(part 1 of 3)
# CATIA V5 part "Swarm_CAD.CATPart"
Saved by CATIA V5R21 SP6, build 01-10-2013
Part number: Final_Swarm
Bounding box of the stored display mesh (mm): x -2100 to 7123.12, y -825.75 to 825.75, z -676.575 to 779.691
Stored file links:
  O:\Swarm_G_March\Swarm_CAD_CATIA.CATPart
  D:\gmarch\Desktop\SWARM\CATPart_single_body.CATPart
  D:\gmarch\Desktop\SWARM\Final_Swarm_for_rendering.CATPart
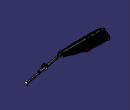
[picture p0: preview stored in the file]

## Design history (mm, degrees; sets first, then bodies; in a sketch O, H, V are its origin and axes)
Set1
  Plane1: type Offset, RefPlane yz-plane, Offset 2945.11
  Sketch1 on Plane1, origin (2945.11, 0, 0), H (0, 1, 0), V (0, 0, 1)
    point P1 (-825.75, -46.32)
    line L1 (-825.75, -46.32) -> (-113.815, 470.931)
    line L2 (-113.815, 470.931) -> (113.815, 470.931)
    line L3 (113.815, 470.931) -> (825.75, -46.32)
    point P4 (825.75, -46.32)
    line L4 (825.75, -46.32) -> (811.0554, -66.5454)
    point P5 (811.0554, -66.5454)
    line L5 (811.0554, -66.5454) -> (665, 39.57)
    point P6 (665, 39.57)
    line L6 (665, 39.57) -> (665, -300)
    line L7 (665, -300) -> (-665, -300)
    line L8 (-665, -300) -> (-665, 39.57)
    point P9 (-665, 39.57)
    line L9 (-665, 39.57) -> (-811.0554, -66.5454)
    point P10 (-811.0554, -66.5454)
    line L10 (-811.0554, -66.5454) -> (-825.75, -46.32)
    distance L7 H = 300
    distance P1 L7 = 253.68
    distance P4 L7 = 253.68
    distance L8 L6 = 1330
    distance L8 V = 665
    angle L1 V = 54
    angle L3 V = 54
    distance P1 P4 = 1651.5
    distance P6 P9 V = 0
    angle L5 L4 = 90
    distance P10 P5 V = 0
    distance L5 L3 = 25
    length L1 = 880
    horizontal: L2 H, L7 H
    vertical: L6 V, L8 V
    perpendicularity: L10 L1
    parallelism: L1 L9
  Sketch2 on end face of Pad1, origin (-2000, 0, 0), H (0, -1, 0), V (0, 0, 1)
    point P1 (-113.815, 470.931)
    line L1 (-113.815, 470.931) -> (-96.1815, 446.6605)
    line L2 (-96.1815, 446.6605) -> (-88.7678, 470.931)
    point P3 (-88.7678, 470.931)
    line L3 (-88.7678, 470.931) -> (-100, 480)
    line L4 (-100, 480) -> (-113.815, 470.931)
    reference projected line E1 (-825.75, -46.32) -> (-113.815, 470.931) from edge [end face of Pad1 | face of Mirror1]
    reference projected point E2 (-113.815, 470.931) from vertex [face of Pad1 from Sketch1.L2 | end face of Pad1 | face of Pad1 from Sketch1.L3]
    reference projected line E3 (-113.815, 470.931) -> (113.815, 470.931) from edge [end face of Pad1 | face of Pad1 from Sketch1.L2]
    reference projected line E4 (-113.815, 470.931) -> (113.815, 470.931) from edge [end face of Pad1 | face of Pad1 from Sketch1.L2]
    angle L1 E1 = 90
    distance L1 E2 = 0
    length L1 = 30
    distance P3 E4 = 0
    length L4 = 16.5258
    angle L3 L4 = 107.799
    length L2 = 25.3775
    coincidence: P1 E3
Body1 (main body)
  Pad1: profile Sketch1, direction (-1, 0, 0), length 4945.11
  Sketch3 on face of Mirror1, origin (3393, 263.2631, 362.3506), H (-0.5878, 0.6545, -0.4755), V (-0.809, -0.4755, 0.3455)
    point P1 (-825.75, -46.32)
    line L1 (-825.75, -46.32) -> (-113.815, 470.931)
    line L2 (-113.815, 470.931) -> (113.815, 470.931)
    line L3 (113.815, 470.931) -> (825.75, -46.32)
    point P4 (825.75, -46.32)
    line L4 (825.75, -46.32) -> (811.0554, -66.5454)
    point P5 (811.0554, -66.5454)
    line L5 (811.0554, -66.5454) -> (665, 39.57)
    point P6 (665, 39.57)
    line L6 (665, 39.57) -> (665, -300)
    line L7 (665, -300) -> (-665, -300)
    line L8 (-665, -300) -> (-665, 39.57)
    point P9 (-665, 39.57)
    line L9 (-665, 39.57) -> (-811.0554, -66.5454)
    point P10 (-811.0554, -66.5454)
    line L10 (-811.0554, -66.5454) -> (-825.75, -46.32)
    distance L7 H = 300
    distance P1 L7 = 253.68
    distance P4 L7 = 253.68
    distance L8 L6 = 1330
    distance L8 V = 665
    angle L1 V = 54
    angle L3 V = 54
    distance P1 P4 = 1651.5
    distance P6 P9 V = 0
    angle L5 L4 = 90
    distance P10 P5 V = 0
    distance L5 L3 = 25
    length L1 = 880
    horizontal: L2 H, L7 H
    vertical: L6 V, L8 V
    perpendicularity: L10 L1
    parallelism: L1 L9
  Sketch4 on start face of Pad1, origin (2945.11, 0, 0), H (0, 1, 0), V (0, 0, 1)
    line L1 (-665, -275) -> (665, -275)
    line L2 (665, -275) -> (665, -300)
    line L3 (665, -300) -> (-665, -300)
    line L4 (-665, -300) -> (-665, -275)
    reference projected line E1 (-665, -300) -> (665, -300) from edge [face of Pad1 from Sketch1.L7 | start face of Pad1]
    reference projected line E2 (665, -300) -> (665, 39.57) from edge [face of Pad1 from Sketch1.L6 | start face of Pad1]
    reference projected line E3 (-665, 39.57) -> (-665, -300) from edge [face of Pad1 from Sketch1.L8 | start face of Pad1]
    distance L1 L3 = 25
    distance L2 E2 = 0
    distance L4 E3 = 0
    horizontal: L1 H, L3 H
    vertical: L2 V, L4 V
    coincidence: L3 E1
  Pocket1: profile Sketch4, direction (-1, 0, 0), up to end face of Pad1
  Sketch5 on face of Pad1 from Sketch1.L8, origin (0, -665, 0), H (1, 0, 0), V (0, 0, 1)
    line L1 (-679, -275) -> (710, -275)
    line L2 (710, -275) -> (710, 5.0715)
    line L3 (710, 5.0715) -> (-679, -275)
    line L4 (-679, -275) -> (-679, -275)
    point P4 (-679, -275)
    reference projected line E1 (-2000, 39.57) -> (-2000, -300) from edge [end face of Pad1 | face of Pad1 from Sketch1.L8]
    reference projected line E2 (2945.11, -275) -> (-2000, -275) from edge [face of Pad1 from Sketch1.L8 | face of Pocket1 from Sketch4.L1]
    reference projected line E3 (2945.11, -275) -> (-2000, -275) from edge [face of Pad1 from Sketch1.L8 | face of Pocket1 from Sketch4.L1]
    reference projected line E4 (-2000, 39.57) -> (-2000, -300) from edge [end face of Pad1 | face of Pad1 from Sketch1.L8]
    reference projected line E5 (2945.11, -275) -> (-2000, -275) from edge [face of Pad1 from Sketch1.L8 | face of Pocket1 from Sketch4.L1]
    distance L4 E1 = 1321
    angle E2 L3 = 168.6
    distance L2 E4 = 2710
    distance L1 E5 = 0
    coincidence: P4 E3
  Pocket2: profile Sketch5, direction (0, 1, 0), up to face of Pad1 from Sketch1.L6
  Sketch6 on face of Pad1 from Sketch1.L8, origin (0, -665, 0), H (1, 0, 0), V (0, 0, 1)
    point P1 (710, 5.0715)
    line L1 (710, 5.0715) -> (710, -275)
    line L2 (710, -275) -> (2945.11, -275)
    line L3 (2945.11, -275) -> (2945.11, 315.2187)
    line L4 (2945.11, 315.2187) -> (710, 5.0715)
    reference projected point E1 (710, 5.0715) from vertex [face of Pad1 from Sketch1.L8 | face of Pocket2 from Sketch5.L2 | face of Pocket2 from Sketch5.L3]
    reference projected line E2 (2945.11, -275) -> (-2000, -275) from edge [face of Pad1 from Sketch1.L8 | face of Pocket1 from Sketch4.L1]
    reference projected line E3 (710, 5.0715) -> (-679, -275) from edge [face of Pad1 from Sketch1.L8 | face of Pocket2 from Sketch5.L3]
    reference projected line E4 (2945.11, 39.57) -> (2945.11, -300) from edge [face of Pad1 from Sketch1.L8 | start face of Pad1]
    angle L4 E3 = 176.5
    vertical: L1 V, L3 V
    coincidence: P1 E1, L2 E2, L3 E4
  Pocket3: profile Sketch6, direction (0, 1, 0), length 2000, mirrored extent
  Sketch7 on face of Pad1 from Sketch1.L1, origin (0, -263.2631, 362.3506), H (1, 0, 0), V (0, 0.809, 0.5878)
    point P1 (710, -695.272)
    line L1 (710, -695.272) -> (845, -695.272)
    line L2 (845, -695.272) -> (2945.11, -199.4883)
    line L3 (2945.11, -199.4883) -> (2945.11, -18.5364)
    line L4 (2945.11, -18.5364) -> (710, -546.1902)
    line L5 (710, -546.1902) -> (710, -695.272)
    point P6 (710, -695.272)
    reference projected line E1 (710, -695.272) -> (710, -607.8395) from edge [face of Pocket3 from Sketch6.L1 | face of Pad1 from Sketch1.L1]
    reference projected point E2 (710, -695.272) from vertex [face of Pad1 from Sketch1.L10 | face of Pad1 from Sketch1.L1 | face of Pocket3 from Sketch6.L1]
    reference projected line E3 (2945.11, 184.728) -> (2945.11, -695.272) from edge [face of Pad1 from Sketch1.L1 | start face of Pad1]
    reference projected line E4 (2945.11, -80.1857) -> (710, -607.8395) from edge [face of Pad1 from Sketch1.L1 | face of Pocket3 from Sketch6.L4]
    distance P1 P6 = 0
    distance E2 P1 = 0
    length L1 = 135
    distance L4 E4 = 60
    horizontal: L1 H
    vertical: L3 V, L5 V
    coincidence: P6 L1, L5 E1, L3 E3
    parallelism: L2 L4
  Pad2: profile Sketch7, direction (0, 0.5878, -0.809), length 30
  Mirror1: of Pad2, about zx-plane
  Sketch8 on zx-plane, origin (0, 0, 0), H (-1, 0, 0), V (0, 0, 1)
    point P1 (-2945.11, 470.931)
    line L1 (-2945.11, 470.931) -> (-7020.0469, -507.3748)
    point P2 (-7020.0469, -507.3748)
    line L2 (-7020.0469, -507.3748) -> (-7025.883, -483.0655)
    line L3 (-7025.883, -483.0655) -> (-7123.12, -506.4101)
    point P4 (-7123.12, -506.4101)
    line L4 (-7123.12, -506.4101) -> (-7082.2671, -676.5748)
    line L5 (-7082.2671, -676.5748) -> (-6985.0301, -653.2303)
    point P6 (-6985.0301, -653.2303)
    line L6 (-6985.0301, -653.2303) -> (-6990.8662, -628.921)
    point P7 (-6990.8662, -628.921)
    line L7 (-6990.8662, -628.921) -> (-2945.11, 300.931)
    point P8 (-2945.11, 300.931)
    line L8 (-2945.11, 300.931) -> (-2945.11, 470.931)
    reference projected line E1 (-2945.11, -46.32) -> (-2945.11, 470.931) from edge [face of Mirror1 | face of Mirror1]
    reference projected point E2 (-2945.11, 470.931) from vertex [face of Mirror1 | face of Pad1 from Sketch1.L2 | face of Mirror1]
    reference projected line E3 (-2945.11, 470.931) -> (2000, 470.931) from edge [face of Mirror1 | face of Pad1 from Sketch1.L2]
    reference projected line E4 (2000, -300) -> (2000, 39.57) from edge [end face of Pad1 | face of Pad1 from Sketch1.L6]
    angle L1 E3 = 13.5
    distance L3 L1 = 25
    distance L6 L4 = 100
    distance P4 E4 = 9123.12
    distance P8 P1 = 170
    distance P7 P2 = 125
    distance L5 P7 = 25
    perpendicularity: L2 L1
    parallelism: L4 L2, L5 L1, L6 L2
    coincidence: P6 L2, L8 E1, P1 E2
    vertical: L8 V
  Pad3: profile Sketch8, direction (0, 1, 0), length 62.5, mirrored extent
  Sketch9 on face of Pad3 from Sketch8.L1, origin (267.3544, 0, 1113.8033), H (0, 1, 0), V (-0.9724, 0, 0.2334)
    point P1 (-85, -2753.8446)
    line L1 (-85, -2753.8446) -> (85, -2753.8446)
    line L2 (85, -2753.8446) -> (62.5, -6944.5716)
    point P3 (62.5, -6944.5716)
    line L3 (62.5, -6944.5716) -> (-62.5, -6944.5716)
    point P4 (-62.5, -6944.5716)
    line L4 (-62.5, -6944.5716) -> (-85, -2753.8446)
    reference projected line E1 (62.5, -2753.8446) -> (-62.5, -2753.8446) from edge [face of Pad1 from Sketch1.L2 | face of Pad3 from Sketch8.L1]
    reference projected line E2 (-62.5, -6944.5716) -> (62.5, -6944.5716) from edge [face of Pad3 from Sketch8.L3 | face of Pad3 from Sketch8.L2]
    reference projected line E3 (62.5, -2753.8446) -> (62.5, -6944.5716) from edge [face of Pad3 from Sketch8.L1 | end face of Pad3]
    reference projected line E4 (-62.5, -2753.8446) -> (-62.5, -6944.5716) from edge [start face of Pad3 | face of Pad3 from Sketch8.L1]
    length L1 = 170
    distance P1 V = 85
    horizontal: L1 H, L3 H
    coincidence: L1 E1, L3 E2, P3 E3, P4 E4
  Pad4: profile Sketch9, direction (-0.2334, 0, -0.9724), length 100
  Sketch10 on face of Pad3 from Sketch8.L7, origin (218.4177, 0, 927.6174), H (0, -1, 0), V (-0.9746, 0, 0.224)
    line L1 (-86, -2697.7824) -> (86, -2697.7824)
    point P2 (86, -2697.7824)
    line L2 (86, -2697.7824) -> (62.5, -6948.7766)
    point P3 (62.5, -6948.7766)
    line L3 (62.5, -6948.7766) -> (-62.5, -6948.7766)
    line L4 (-62.5, -6948.7766) -> (-86, -2697.7824)
    reference projected line E1 (62.5, -6948.7766) -> (-62.5, -6948.7766) from edge [face of Pad3 from Sketch8.L6 | face of Pad3 from Sketch8.L5]
    reference projected line E2 (62.5, -2797.7824) -> (-62.5, -2797.7824) from edge [face of Pad3 from Sketch8.L8 | face of Pad3 from Sketch8.L7]
    distance P2 V = 86
    length L1 = 172
    length L3 = 125
    distance P3 E1 = 0
    distance P3 V = 62.5
    distance L1 E2 = 100
    horizontal: L3 H, L1 H
  Pad5: profile Sketch10, direction (0.224, 0, 0.9746), length 80.5
  Sketch11 on face of Pad4 from Sketch9.L2, origin (0.5196, 99.7823, -0.1276), H (-1, 0.0052, 0), V (0, 0.0013, 1)
    point P1 (-2944.6246, 471.0597)
    line L1 (-2944.6246, 471.0597) -> (-2944.6246, 301.0598)
    line L2 (-2944.6246, 301.0598) -> (-6990.446, -628.794)
    line L3 (-6990.446, -628.794) -> (-7019.6262, -507.2477)
    line L4 (-7019.6262, -507.2477) -> (-2943.5913, 471.3077)
    line L5 (-2943.5913, 471.3077) -> (-2944.6246, 471.0597)
    reference projected line E1 (-7024.8073, -508.4915) -> (-2944.6274, 471.059) from edge [face of Pad4 from Sketch9.L2 | face of Pad4]
    reference projected line E2 (-2847.1645, 323.4591) -> (-6994.5587, -629.7392) from edge [face of Pad5 from Sketch10.L4 | face of Pad5]
    reference projected line E3 (-7014.5006, -528.5976) -> (-7020.3367, -504.2883) from edge [face of Pad3 from Sketch8.L2 | end face of Pad3]
    reference projected point E4 (-2944.6246, 383.6585) from vertex [end face of Pad5 | face of Pad5 from Sketch10.L4 | face of Mirror1]
    distance L3 E3 = 0
    distance L1 E4 = 0
    vertical: L1 V
    coincidence: L4 P1, L4 E1, L2 E2
    parallelism: L5 L4
  Pad6: profile Sketch11, direction (0.0052, 1, -0.0013), length 1, mirrored extent
  Mirror2: of Pad6, about zx-plane
  Sketch12 on zx-plane, origin (0, 0, 0), H (-1, 0, 0), V (0, 0, 1)
    point P1 (-7123.12, -506.4101)
    line L1 (-7123.12, -506.4101) -> (-7025.883, -483.0655)
    point P2 (-7025.883, -483.0655)
    line L2 (-7025.883, -483.0655) -> (-6985.0301, -653.2303)
    point P3 (-6985.0301, -653.2303)
    line L3 (-6985.0301, -653.2303) -> (-7082.2671, -676.5748)
    line L4 (-7082.2671, -676.5748) -> (-7123.12, -506.4101)
    reference projected point E1 (-7025.883, -483.0655) from vertex [end face of Pad3 | face of Pad3 from Sketch8.L3 | face of Pad3 from Sketch8.L2]
    reference projected point E2 (-7123.12, -506.4101) from vertex [face of Pad3 from Sketch8.L3 | face of Pad3 from Sketch8.L4 | end face of Pad3]
    reference projected point E3 (-6985.0301, -653.2303) from vertex [face of Pad3 from Sketch8.L5 | face of Pad3 from Sketch8.L6 | end face of Pad3]
    perpendicularity: L3 L2, L4 L1
    coincidence: P2 E1, P1 E2, P3 E3
  Pad7: profile Sketch12, direction (0, 1, 0), length 162.5, mirrored extent
  Sketch13 on zx-plane, origin (0, 0, 0), H (-1, 0, 0), V (0, 0, 1)
    line L1 (-7025.883, -483.0655) -> (-6977.2645, -471.3932)
    line L2 (-6977.2645, -471.3932) -> (-6936.4116, -641.558)
    line L3 (-6936.4116, -641.558) -> (-6985.0301, -653.2303)
    line L4 (-6985.0301, -653.2303) -> (-7025.883, -483.0655)
    reference projected line E1 (-7014.9212, -528.7247) -> (-6985.7405, -650.271) from edge [face of Pad7 | end face of Pad6]
    reference projected point E2 (-6985.0301, -653.2303) from edge [face of Pad7 | face of Pad7]
    reference projected point E3 (-7025.883, -483.0655) from edge [face of Pad7 | face of Pad7]
    reference projected line E4 (-7031.1915, -484.34) -> (-7128.4285, -507.6845) from edge [face of Pad7 from Sketch12.L1 | end face of Pad7]
    distance L4 E1 = 0
    distance L2 L4 = 50
    distance L3 E2 = 0
    distance L1 E3 = 0
    length L3 = 50
    parallelism: L1 E4
  Pad8: profile Sketch13, direction (0, 1, 0), length 70, mirrored extent
  Plane2: type 2Lines, Element1 edge [face of Pad8 from Sketch13.L2 | end face of Pad8], Element2 edge [face of Pad7 | end face of Pad7]
  Sketch14 on Plane2, origin (5153.1642, -2868.2892, -1265.7369), H (0.4859, 0.874, 0.0001), V (0.1794, -0.0999, 0.9787)
    line L1 (3558.9921, 799.3176) -> (3539.1233, 625.4492)
    line L2 (3539.1233, 625.4492) -> (3434.6545, 637.3874)
    line L3 (3434.6545, 637.3874) -> (3454.5233, 811.2558)
    line L4 (3454.5233, 811.2558) -> (3558.9921, 799.3176)
    reference projected line E1 (3432.1913, 615.8329) -> (3452.0602, 789.7013) from edge [face of Pad8 from Sketch13.L2 | end face of Pad8]
    reference projected line E2 (3536.6304, 603.6346) -> (3556.4992, 777.503) from edge [face of Pad7 from Sketch12.L2 | end face of Pad7]
    reference projected point E3 (3458.2766, 634.688) from vertex [end face of Pad8 | face of Pad7 | face of Pad8]
    reference projected point E4 (3478.1454, 808.5564) from vertex [end face of Pad8 | face of Pad7 | face of Pad8]
    perpendicularity: L2 L1
    parallelism: L3 L1, L4 L2
    coincidence: L3 E1, L1 E2, L2 E3, L4 E4
  Pad9: profile Sketch14, direction (0.8554, -0.4755, -0.2054), length 70
  Mirror3: of Pad9, about zx-plane
  Plane3: type Offset, RefPlane zx-plane, Offset 15
  Sketch15 on Plane3, origin (0, 15, 0), H (-1, 0, 0), V (0, 0, 1)
    line L1 (-3516.4485, 346.1058) -> (-3376.5384, 379.6952)
    line L2 (-3376.5384, 379.6952) -> (-3234.193, 723.3474)
    arc A1 centre (-3148.9859, 688.0534) radius 92.2274 from (-3234.193, 723.3474) to (-3077.4439, 746.2569) cw
    line L3 (-3077.4439, 746.2569) -> (-2927.9542, 470.931)
    line L4 (-2927.9542, 470.931) -> (-2941.6089, 470.931)
    line L5 (-2941.6089, 470.931) -> (-3080.2319, 726.2429)
    arc A2 centre (-3149.8835, 688.4252) radius 79.256 from (-3080.2319, 726.2429) to (-3223.1064, 718.7552) ccw
    point P9 (-3149.8835, 688.4252)
    line L6 (-3223.1064, 718.7552) -> (-3367.7917, 369.4541)
    point P11 (-3367.7917, 369.4541)
    line L7 (-3367.7917, 369.4541) -> (-3513.6471, 334.4373)
    line L8 (-3513.6471, 334.4373) -> (-3516.4485, 346.1058)
    reference projected line E1 (-2945.1123, 470.9305) -> (-7025.2333, -508.6199) from edge [face of Mirror2 | end face of Pad6]
    reference projected point E2 (-7082.2671, -676.5748) from vertex [face of Pad7 from Sketch12.L4 | face of Pad7 from Sketch12.L3 | start face of Pad7]
    reference projected line E3 (-2945.1123, 470.9305) -> (-7025.2333, -508.6199) from edge [face of Mirror2 | face of Mirror2]
    reference projected line E4 (-2945.11, 470.931) -> (2000, 470.931) from edge [face of Mirror1 | face of Pad1 from Sketch1.L2]
    distance A2 A1 = 12
    distance L6 L2 = 12
    distance L3 L5 = 12
    distance L7 L1 = 12
    angle L7 L8 = 90
    distance L8 P11 = 150
    angle L2 L1 = 126
    radius A1 = 92.2274
    radius A2 = 79.256
    distance P9 E2 V = 1365
    angle L3 E3 = 105
    tangency: A1 L2, A2 L5, L6 A2
    coincidence: L7 E1, L4 E4
    parallelism: L5 L3
  Pad10: profile Sketch15, direction (0, 1, 0), length 36, mirrored extent
  Sketch16 on face of Pad1 from Sketch1.L2, origin (0, 0, 470.931), H (1, 0, 0), V (0, 1, 0)
    circle A1 centre (-350, 0) radius 80
    point P1 (-350, 0)
    circle A2 centre (-50, 0) radius 80
    point P2 (-50, 0)
    reference projected line E1 (-2000, 113.815) -> (-2000, -113.815) from edge [end face of Pad1 | face of Pad1 from Sketch1.L2]
    reference projected line E2 (-2000, 113.815) -> (-2000, -113.815) from edge [end face of Pad1 | face of Pad1 from Sketch1.L2]
    circle A3 centre (-50, 0) radius 70
    circle A4 centre (-350, 0) radius 70
    radius A2 = 80
    radius A1 = 80
    distance P1 E1 = 1650
    distance P2 E2 = 1950
    distance A4 A1 = 10
    distance A3 A2 = 10
    coincidence: P1 H, P2 H
  Pad11: profile Sketch16, direction (0, 0, 1), length 24
  Sketch17 on face of Pad1 from Sketch1.L2, origin (0, 0, 470.931), H (1, 0, 0), V (0, 1, 0)
    circle A1 centre (-350, 0) radius 10
    point P1 (-350, 0)
    circle A2 centre (-50, 0) radius 10
    point P2 (-50, 0)
    reference projected circle E1 centre (-50, 0) radius 70 from edge [end face of Pad11 | face of Pad11 from Sketch16.A3]
    reference projected circle E2 centre (-350, 0) radius 70 from edge [end face of Pad11 | face of Pad11 from Sketch16.A4]
    radius A1 = 10
    radius A2 = 10
    coincidence: P1 H, P2 H
    concentricity: A2 E1, A1 E2
  Pad12: profile Sketch17, direction (0, 0, 1), length 8
  Sketch18 on end face of Pad12, origin (0, 0, 478.931), H (1, 0, 0), V (0, 1, 0)
    circle A1 centre (-350, 0) radius 50
    point P1 (-350, 0)
    circle A2 centre (-50, 0) radius 50
    point P2 (-50, 0)
    reference projected circle E1 centre (-50, 0) radius 10 from edge [face of Pad12 from Sketch17.A2 | end face of Pad12]
    reference projected circle E2 centre (-350, 0) radius 10 from edge [face of Pad12 from Sketch17.A1 | end face of Pad12]
    radius A2 = 50
    radius A1 = 50
    coincidence: P1 H, P2 H
    concentricity: A2 E1, A1 E2
  Pad13: profile Sketch18, direction (0, 0, 1), length 2
  Sketch19 on end face of Pad13, origin (0, 0, 480.931), H (1, 0, 0), V (0, 1, 0)
    circle A1 centre (-350, 0) radius 10
    point P1 (-350, 0)
    circle A2 centre (-50, 0) radius 10
    point P2 (-50, 0)
    reference projected circle E1 centre (-50, 0) radius 50 from edge [face of Pad13 from Sketch18.A2 | end face of Pad13]
    reference projected circle E2 centre (-350, 0) radius 50 from edge [face of Pad13 from Sketch18.A1 | end face of Pad13]
    radius A2 = 10
    radius A1 = 10
    coincidence: P1 H, P2 H
    concentricity: A2 E1, A1 E2
  Pad14: profile Sketch19, direction (0, 0, 1), length 8
  Sketch20 on end face of Pad14, origin (0, 0, 488.931), H (1, 0, 0), V (0, 1, 0)
    circle A1 centre (-350, 0) radius 35
    point P1 (-350, 0)
    circle A2 centre (-50, 0) radius 35
    point P2 (-50, 0)
    reference projected circle E1 centre (-350, 0) radius 50 from edge [face of Pad13 from Sketch18.A1 | end face of Pad13]
    reference projected circle E2 centre (-50, 0) radius 50 from edge [face of Pad13 from Sketch18.A2 | end face of Pad13]
    radius A2 = 35
    radius A1 = 35
    coincidence: P1 H, P2 H
    concentricity: A1 E1, E2 A2
  Pad15: profile Sketch20, direction (0, 0, 1), length 2
  Pocket4: profile Sketch2, direction (1, 0, 0), length 4964
  Mirror4: of Pocket4, Sketch2, about zx-plane
  Sketch21 on face of Pad1 from Sketch1.L2, origin (0, 0, 470.931), H (1, 0, 0), V (0, 1, 0)
    circle A1 centre (-1626, 0) radius 43
    point P1 (-1626, 0)
    reference projected line E1 (-2000, 113.815) -> (-2000, -113.815) from edge [end face of Pad1 | face of Pad1 from Sketch1.L2]
    circle A2 centre (-1626, 0) radius 33
    distance P1 E1 = 374
    radius A1 = 43
    distance A2 A1 = 10
    coincidence: P1 H
  Pad16: profile Sketch21, direction (0, 0, 1), length 40
  Sketch22 on face of Pad1 from Sketch1.L2, origin (0, 0, 470.931), H (1, 0, 0), V (0, 1, 0)
    circle A1 centre (-1626, 0) radius 10
    point P1 (-1626, 0)
    reference projected circle E1 centre (-1626, 0) radius 33 from edge [end face of Pad16 | face of Pad16 from Sketch21.A2]
    radius A1 = 10
    coincidence: P1 H
    concentricity: A1 E1
  Pad17: profile Sketch22, direction (0, 0, 1), length 10
  Sketch23 on end face of Pad17, origin (0, 0, 480.931), H (1, 0, 0), V (0, 1, 0)
    circle A1 centre (-1626, 0) radius 25
    point P1 (-1626, 0)
    reference projected circle E1 centre (-1626, 0) radius 10 from edge [face of Pad17 from Sketch22.A1 | end face of Pad17]
    radius A1 = 25
    coincidence: P1 H
    concentricity: A1 E1
  Pad18: profile Sketch23, direction (0, 0, 1), length 2
  Sketch24 on end face of Pad18, origin (0, 0, 482.931), H (1, 0, 0), V (0, 1, 0)
    circle A1 centre (-1626, 0) radius 10
    point P1 (-1626, 0)
    reference projected circle E1 centre (-1626, 0) radius 33 from edge [end face of Pad16 | face of Pad16 from Sketch21.A2]
    radius A1 = 10
    coincidence: P1 H
    concentricity: A1 E1
  Pad19: profile Sketch24, direction (0, 0, 1), length 23
  Sketch25 on end face of Pad19, origin (0, 0, 505.931), H (1, 0, 0), V (0, 1, 0)
    circle A1 centre (-1626, 0) radius 23
    point P1 (-1626, 0)
    reference projected circle E1 centre (-1626, 0) radius 43 from edge [face of Pad16 from Sketch21.A1 | end face of Pad16]
    radius A1 = 23
    coincidence: P1 H
    concentricity: A1 E1
  Pad20: profile Sketch25, direction (0, 0, 1), up to end face of Pad16
  Chamfer1: length 20, angle 45, on edge [start face of Pad7 | face of Mirror3] (x2); edge [face of Mirror3 | end face of Pad7] (x2)
  Chamfer2: length 25, angle 45, on edge [end face of Pad1 | face of Pad1 from Sketch1.L2]
  Sketch26 on face of Pad1 from Sketch1.L2, origin (0, 0, 470.931), H (1, 0, 0), V (0, 1, 0)
    line L1 (-1087, 23.5) -> (-993, 23.5)
    line L2 (-993, 23.5) -> (-993, -23.5)
    line L3 (-993, -23.5) -> (-1087, -23.5)
    line L4 (-1087, -23.5) -> (-1087, 23.5)
    reference projected line E1 (-2000, 95.6515) -> (-2000, -95.6515) from edge [end face of Pad1 | face of Chamfer2]
    length L1 = 94
    distance L3 L1 = 47
    distance L1 H = 23.5
    distance L4 E1 = 913
    horizontal: L1 H, L3 H
    vertical: L2 V, L4 V
  Pad21: profile Sketch26, direction (0, 0, 1), length 32
  Sketch27 on end face of Pad21, origin (0, 0, 502.931), H (1, 0, 0), V (0, 1, 0)
    line L1 (-1083.5, 20) -> (-1043.5, 20)
    line L2 (-1043.5, 20) -> (-1043.5, -20)
    line L3 (-1043.5, -20) -> (-1083.5, -20)
    line L4 (-1083.5, -20) -> (-1083.5, 20)
    point P5 (-1036.5, 20)
    line L5 (-1036.5, 20) -> (-996.5, 20)
    line L6 (-996.5, 20) -> (-996.5, -20)
    line L7 (-996.5, -20) -> (-1036.5, -20)
    line L8 (-1036.5, -20) -> (-1036.5, 20)
    reference projected line E1 (-1087, -23.5) -> (-993, -23.5) from edge [face of Pad21 from Sketch26.L3 | end face of Pad21]
    reference projected line E2 (-993, -23.5) -> (-993, 23.5) from edge [face of Pad21 from Sketch26.L2 | end face of Pad21]
    reference projected line E3 (-1087, 23.5) -> (-1087, -23.5) from edge [face of Pad21 from Sketch26.L4 | end face of Pad21]
    distance L5 L7 = 40
    distance L4 L2 = 40
    distance L8 L6 = 40
    distance L7 L3 = 0
    distance L3 E1 = 3.5
    distance L6 E2 = 3.5
    distance L4 E3 = 3.5
    horizontal: L1 H, L3 H, L5 H, L7 H
    vertical: L2 V, L4 V, L6 V, L8 V
    coincidence: P5 L1
  Pad22: profile Sketch27, direction (0, 0, 1), length 3
  Sketch28 on face of Pad2, origin (0, -263.2631, 362.3506), H (1, 0, 0), V (0, 0.809, 0.5878)
    line L1 (-1516, 184.728) -> (-1736, 184.728)
    line L2 (-1736, 184.728) -> (-1736, 153.328)
    line L3 (-1736, 153.328) -> (-1516, 153.328)
    line L4 (-1516, 153.328) -> (-1516, 184.728)
    reference projected line E1 (2945.11, 184.728) -> (-2000, 184.728) from edge [face of Mirror4 | face of Pad2]
    reference projected line E2 through (-1626, 0) direction (0, 1) from axis of face of Pad16 from Sketch21.A1
    point P5 (-468, 184.728)
    line L5 (-468, 184.728) -> (60, 184.728)
    line L6 (60, 184.728) -> (60, 153.328)
    line L7 (60, 153.328) -> (-468, 153.328)
    line L8 (-468, 153.328) -> (-468, 184.728)
    reference projected curve E3 from edge [face of Pad11 from Sketch16.A1 | end face of Pad11]
    line L9 (-2000, -558.272) -> (-1602.5, -558.272)
    point P10 (-1602.5, -558.272)
    line L10 (-1602.5, -558.272) -> (-1327, -695.272)
    point P11 (-1327, -695.272)
    line L11 (-1327, -695.272) -> (-2000, -695.272)
    line L12 (-2000, -695.272) -> (-2000, -558.272)
    reference projected line E4 (-2000, 184.728) -> (2964, 184.728) from edge [face of Mirror4 | face of Mirror4]
    reference projected line E5 (-2000, 184.728) -> (-2000, -695.272) from edge [end face of Pad1 | face of Pad2]
    reference projected line E6 (2945.11, -695.272) -> (-2000, -695.272) from edge [face of Pad2 | face of Pad2]
    reference projected line E7 (-2000, 184.728) -> (-2000, -695.272) from edge [end face of Pad1 | face of Pad2]
    reference projected line E8 (-2000, 184.728) -> (-2000, -695.272) from edge [end face of Pad1 | face of Pad2]
    point P13 (-286, -695.272)
    line L13 (-286, -695.272) -> (-209, -655.272)
    point P14 (-209, -655.272)
    line L14 (-209, -655.272) -> (-209, -530.272)
    line L15 (-209, -530.272) -> (-24, -530.272)
    line L16 (-24, -530.272) -> (-24, -621.272)
    line L17 (-24, -621.272) -> (682.5, -621.272)
    line L18 (682.5, -621.272) -> (682.5, 153.328)
    line L19 (682.5, 153.328) -> (645, 153.328)
    line L20 (645, 153.328) -> (645, 184.728)
    point P21 (645, 184.728)
    line L21 (645, 184.728) -> (740, 184.728)
    line L22 (740, 184.728) -> (740, 153.328)
    point P23 (740, 153.328)
    line L23 (740, 153.328) -> (692.5, 153.328)
    line L24 (692.5, 153.328) -> (692.5, -695.272)
    point P25 (692.5, -695.272)
    line L25 (692.5, -695.272) -> (-286, -695.272)
    reference projected line E9 (-2000, 184.728) -> (-2000, -695.272) from edge [end face of Pad1 | face of Pad2]
    reference projected line E10 (-2000, 184.728) -> (-2000, -695.272) from edge [end face of Pad1 | face of Pad2]
    reference projected line E11 (-2000, 184.728) -> (-2000, -695.272) from edge [end face of Pad1 | face of Pad2]
    distance L1 E1 = 0
    distance L3 L1 = 31.4
    length L3 = 220
    distance L2 E2 = 110
    length L7 = 528
    distance L7 L5 = 31.4
    distance L8 E3 = 38
    distance L9 E4 = 743
    distance L12 E5 = 0
    distance L11 E6 = 0
    distance P10 E7 = 397.5
    distance P11 E8 = 673
    distance P13 E9 = 1714
    distance P14 E10 = 1791
    length L15 = 185
    distance L15 L25 = 165
    distance L17 L25 = 74
    length L14 = 125
    distance L20 L22 = 95
    distance L18 L24 = 10
    distance L19 L21 = 31.4
    distance L18 E11 = 2682.5
    distance L18 L20 = 37.5
    horizontal: L1 H, L3 H, L5 H, L7 H, L9 H, L11 H, L15 H, L17 H, L19 H, L21 H, L23 H, L25 H
    vertical: L2 V, L4 V, L6 V, L8 V, L12 V, L14 V, L16 V, L18 V, L20 V, L22 V, L24 V
    coincidence: P5 L1, P13 L11, P21 L1, P23 L19, P25 L11
  Pocket5: profile Sketch28, direction (0, 0.5878, -0.809), length 30
  Mirror5: of Pocket5, about zx-plane
  Sketch29 on face of Pad2, origin (0, -263.2631, 362.3506), H (1, 0, 0), V (0, 0.809, 0.5878)
    line L1 (692.5, -621.272) -> (845, -621.272)
    point P2 (845, -621.272)
    line L2 (845, -621.272) -> (2945.11, -125.4883)
    line L3 (2945.11, -125.4883) -> (2945.11, -199.4883)
    line L4 (2945.11, -199.4883) -> (845, -695.272)
    point P5 (845, -695.272)
    line L5 (845, -695.272) -> (692.5, -695.272)
    line L6 (692.5, -695.272) -> (692.5, -621.272)
    reference projected line E1 (682.5, -621.272) -> (-24, -621.272) from edge [face of Pad2 | face of Pocket5 from Sketch28.L17]
    reference projected line E2 (692.5, -695.272) -> (692.5, 153.328) from edge [face of Pad2 | face of Pocket5 from Sketch28.L24]
    reference projected line E3 (845, -695.272) -> (710, -695.272) from edge [face of Pad2 | face of Pad2]
    reference projected line E4 (845, -695.272) -> (2945.11, -199.4883) from edge [face of Pad2 from Sketch7.L2 | face of Pad2]
    reference projected line E5 (2945.11, 184.728) -> (2945.11, -695.272) from edge [face of Pad2 | face of Mirror1]
    distance L1 E1 = 0
    distance L6 E2 = 0
    distance L5 E3 = 0
    distance P2 P5 H = 0
    distance L3 E5 = 0
    horizontal: L1 H, L5 H
    vertical: L3 V, L6 V
    coincidence: L4 E4
    parallelism: L2 L4
  Pocket6: profile Sketch29, direction (0, 0.5878, -0.809), length 30
  Mirror6: of Pocket6, about zx-plane
  Sketch30 on end face of Pad1, origin (-2000, 0, 0), H (0, -1, 0), V (0, 0, 1)
    point P1 (257.0868, 317.3953)
    line L1 (257.0868, 317.3953) -> (218.8807, 264.8092)
    line L2 (218.8807, 264.8092) -> (275.5119, 223.6642)
    line L3 (275.5119, 223.6642) -> (313.718, 276.2503)
    line L4 (313.718, 276.2503) -> (257.0868, 317.3953)
    reference projected line E1 (113.815, 470.931) -> (825.75, -46.32) from edge [end face of Pad1 | face of Pad2]
    reference projected point E2 (113.815, 470.931) from vertex [end face of Pad1 | face of Mirror4 | face of Pad2]
    line L5 (336, -210) -> (406, -210)
    line L6 (406, -210) -> (406, -275)
    line L7 (406, -275) -> (336, -275)
    line L8 (336, -275) -> (336, -210)
    reference projected line E3 (665, -275) -> (-665, -275) from edge [end face of Pad1 | face of Pocket1 from Sketch4.L1]
    line L9 (618, -63) -> (670, -63)
    line L10 (670, -63) -> (670, -115)
    line L11 (670, -115) -> (618, -115)
    line L12 (618, -115) -> (618, -63)
    reference projected line E4 (665, -275) -> (-665, -275) from edge [end face of Pad1 | face of Pocket1 from Sketch4.L1]
    reference projected line E5 (665, 39.57) -> (665, -300) from edge [end face of Pad1 | face of Pad1 from Sketch1.L8]
    circle A1 centre (643.5, -160) radius 22.5
    point P13 (643.5, -160)
    distance L3 L1 = 70
    distance L4 L2 = 65
    distance L4 E1 = 40
    distance P1 E2 = 210
    distance L5 L7 = 65
    distance L6 L8 = 70
    distance L7 E3 = 0
    distance L8 V = 336
    length L9 = 52
    distance L9 L11 = 52
    distance L11 E4 = 160
    distance L10 E5 = 5
    radius A1 = 22.5
    distance P13 L10 = 26.5
    distance P13 L11 = 45
    perpendicularity: L2 L1
    horizontal: L5 H, L7 H, L9 H, L11 H
    vertical: L6 V, L8 V, L10 V, L12 V
  Pad23: profile Sketch30, direction (-1, 0, 0), length 10
  Mirror7: of Pad23, about zx-plane
  Sketch31 on end face of Pad1, origin (-2000, 0, 0), H (0, -1, 0), V (0, 0, 1)
    line L1 (410, 83) -> (444, 83)
    line L2 (444, 83) -> (444, 19)
    line L3 (444, 19) -> (410, 19)
    line L4 (410, 19) -> (410, 83)
    reference projected line E1 (665, -275) -> (-665, -275) from edge [end face of Pad1 | face of Mirror7]
    distance L1 L3 = 64
    distance L2 L4 = 34
    distance L4 V = 410
    distance L3 E1 = 294
    horizontal: L1 H, L3 H
    vertical: L2 V, L4 V
  Pocket7: profile Sketch31, direction (1, 0, 0), length 10
  Mirror8: of Pocket7, about zx-plane
  Sketch32 on end face of Pocket7, origin (-1990, 0, 0), H (0, -1, 0), V (0, 0, 1)
    circle A1 centre (427, 68) radius 10
    point P1 (427, 68)
    circle A2 centre (427, 34) radius 10
    point P2 (427, 34)
    reference projected line E1 (444, 83) -> (410, 83) from edge [end face of Pad1 | face of Pocket7 from Sketch31.L1]
    reference projected line E2 (410, 83) -> (410, 19) from edge [end face of Pad1 | face of Pocket7 from Sketch31.L4]
    reference projected line E3 (410, 19) -> (444, 19) from edge [end face of Pad1 | face of Pocket7 from Sketch31.L3]
    distance P1 E1 = 15
    distance P1 E2 = 17
    distance P2 P1 H = 0
    distance P2 E3 = 15
  Pad24: profile Sketch32, direction (-1, 0, 0), length 10
  Mirror9: of Pad24, about zx-plane
  Sketch33 on end face of Pad1, origin (-2000, 0, 0), H (0, -1, 0), V (0, 0, 1)
    line L1 (99.1204, 450.7056) -> (700.22, 13.9812)
    line L2 (700.22, 13.9812) -> (697.2811, 9.9361)
    line L3 (697.2811, 9.9361) -> (96.1815, 446.6605)
    line L4 (96.1815, 446.6605) -> (99.1204, 450.7056)
    reference projected line E1 (803.2947, -60.907) -> (692.4594, 19.6196) from edge [face of Pocket5 from Sketch28.L10 | face of Pad2]
    reference projected line E2 (722.6753, 44.8882) -> (707.9807, 24.6627) from edge [end face of Pad1 | face of Pocket5 from Sketch28.L9]
    reference projected line E3 (103.9421, 457.3421) -> (121.5757, 481.6126) from edge [end face of Pad1 | face of Mirror4]
    distance L3 L1 = 5
    distance L1 E1 = 0
    distance L2 E2 = 0
    distance L4 E3 = 0
    perpendicularity: L2 L1
  Pocket8: profile Sketch33, direction (1, 0, 0), length 5
  Mirror10: of Pocket8, about zx-plane
  Sketch34 on end face of Pad1, origin (-2000, 0, 0), H (0, -1, 0), V (0, 0, 1)
    line L1 (-125, 201) -> (125, 201)
    line L2 (125, 201) -> (125, -85)
    line L3 (125, -85) -> (-125, -85)
    line L4 (-125, -85) -> (-125, 201)
    reference projected line E1 (665, -275) -> (406, -275) from edge [end face of Pad1 | face of Mirror7]
    length L4 = 286
    length L1 = 250
    distance L3 E1 = 190
    distance L4 V = 125
    horizontal: L1 H, L3 H
    vertical: L2 V, L4 V
  Pad25: profile Sketch34, direction (-1, 0, 0), length 57
  Sketch35 on end face of Pad25, origin (-2057, 0, 0), H (0, -1, 0), V (0, 0, 1)
    point P1 (-175.25, 169.6)
    line L1 (-145.25, 169.6) -> (145.25, 169.6)
    line L2 (175.25, 139.6) -> (175.25, -29)
    line L3 (145.25, -59) -> (-145.25, -59)
    line L4 (-175.25, -29) -> (-175.25, 139.6)
    point P2 (175.25, 169.6)
    reference projected line E1 (665, -275) -> (406, -275) from edge [end face of Pad1 | face of Mirror7]
    arc A1 centre (-145.25, 139.6) radius 30 from (-175.25, 139.6) to (-145.25, 169.6) cw
    arc A2 centre (145.25, 139.6) radius 30 from (145.25, 169.6) to (175.25, 139.6) cw
    arc A3 centre (145.25, -29) radius 30 from (145.25, -59) to (175.25, -29) ccw
    arc A4 centre (-145.25, -29) radius 30 from (-145.25, -59) to (-175.25, -29) cw
    distance L4 V = 175.25
    distance L1 L3 = 228.6
    distance L3 E1 = 216
    distance P1 P2 = 350.5
    radius A1 = 30
    radius A2 = 30
    radius A3 = 30
    radius A4 = 30
    horizontal: L1 H, L3 H
    vertical: L2 V, L4 V
    coincidence: L4 P1, L1 P1, L1 P2, L2 P2
    tangency: A1 L4, A1 L1, A2 L1, A2 L2, A3 L3, A3 L2, A4 L3, A4 L4
  Pad26: profile Sketch35, direction (-1, 0, 0), length 5
  Chamfer3: length 51, angle 27, on edge [face of Pad25 from Sketch34.L3 | end face of Pad25]; edge [face of Pad25 from Sketch34.L1 | end face of Pad25]
  Sketch36 on end face of Pad26, origin (-2062, 0, 0), H (0, -1, 0), V (0, 0, 1)
    point P1 (0, 72)
    line L1 (0, 72) -> (52, 72)
    point P3 (0, 16)
    arc A1 centre (0, 44) radius 28 from (0, 16) to (0, 72) cw
    point P4 (0, 44)
    line L2 (0, 16) -> (52, 16)
    arc A2 centre (52, 44) radius 28 from (52, 16) to (52, 72) ccw
    reference projected line E1 (-145.25, -59) -> (145.25, -59) from edge [face of Pad26 from Sketch35.L3 | end face of Pad26]
    construction line L3 through (-121.1855, 149.5495) direction (0, 1)
    construction line L4 through (0, 149.5495) direction (1, 0)
    line L5 (-98, 44) -> (-98, 96)
    arc A3 centre (-70, 44) radius 28 from (-42, 44) to (-98, 44) cw
    line L6 (-42, 44) -> (-42, 96)
    arc A4 centre (-70, 96) radius 28 from (-42, 96) to (-98, 96) ccw
    point P9 (-121.1855, 149.5495)
    point P11 (-70, 44)
    distance A2 A1 = 108
    distance L1 L2 = 56
    distance L2 E1 = 75
    distance A4 A3 = 108
    distance L5 L6 = 56
    angle L6 V = 0
    distance P11 P4 V = 0
    distance P11 P4 = 70
    coincidence: P1 V, P3 V
    horizontal: L1 H
    tangency: A1 L1, L2 A1, A2 L1, A2 L2, A3 L5, L6 A3, A4 L5, A4 L6
  Pad27: profile Sketch36, direction (-1, 0, 0), length 28
  Fillet1: radius 28, on end face of Pad27
  Sketch37 on end face of Pad1, origin (-2000, 0, 0), H (0, -1, 0), V (0, 0, 1)
    line L1 (-25, 445.931) -> (25, 445.931)
    line L2 (25, 445.931) -> (25, 400.931)
    line L3 (25, 400.931) -> (-25, 400.931)
    line L4 (-25, 400.931) -> (-25, 445.931)
    reference projected line E1 (-95.6515, 445.931) -> (95.6515, 445.931) from edge [end face of Pad1 | face of Chamfer2]
    line L5 (-665, -205) -> (-605, -205)
    line L6 (-605, -205) -> (-605, -315)
    line L7 (-605, -315) -> (-665, -315)
    line L8 (-665, -315) -> (-665, -205)
    point P9 (605, -205)
    line L9 (605, -205) -> (665, -205)
    line L10 (665, -205) -> (665, -315)
    line L11 (665, -315) -> (605, -315)
    line L12 (605, -315) -> (605, -205)
    point P11 (665, -315)
    reference projected line E2 (665, 39.57) -> (665, -300) from edge [end face of Pad1 | face of Pad1 from Sketch1.L8]
    reference projected line E3 (-665, -300) -> (-665, 39.57) from edge [end face of Pad1 | face of Pad1 from Sketch1.L6]
    reference projected line E4 (665, -275) -> (406, -275) from edge [end face of Pad1 | face of Mirror7]
    distance E1 L1 = 0
    distance L2 V = 25
    distance L4 V = 25
    distance L3 L1 = 45
    distance L12 L10 = 60
    distance L9 L11 = 110
    distance L10 E2 = 0
    distance L8 E3 = 0
    distance L7 E4 = 40
    distance L6 L8 = 60
    horizontal: L1 H, L3 H, L5 H, L7 H, L9 H, L11 H
    vertical: L2 V, L4 V, L6 V, L8 V, L10 V, L12 V
    coincidence: P9 L5, P11 L7
  Pad28: profile Sketch37, direction (-1, 0, 0), length 80
  Chamfer4: length 33, angle 10, on edge [face of Pad28 from Sketch37.L3 | end face of Pad28]; edge [face of Pad28 from Sketch37.L1 | end face of Pad28]
  Sketch38 on end face of Pad28, origin (-2080, 0, 0), H (0, -1, 0), V (0, 0, 1)
    point P1 (0, 400)
    line L1 (0, 400) -> (-36.5609, 400)
    line L2 (-36.5609, 400) -> (-75.1979, 410.3528)
    line L3 (-75.1979, 410.3528) -> (-94.5679, 445.3499)
    arc A1 centre (-87.1944, 449.431) radius 8.4276 from (-94.5679, 445.3499) to (-82.2888, 456.2838) cw
    point P5 (-87.1944, 449.431)
    line L4 (-82.2888, 456.2838) -> (-43.6518, 445.931)
    line L5 (-43.6518, 445.931) -> (0, 445.931)
    point P8 (0, 445.931)
    line L6 (0, 445.931) -> (0, 400)
    circle A2 centre (-87.1944, 449.431) radius 3.5
    point P9 (-87.1944, 445.931)
    reference projected line E1 (-95.6515, 445.931) -> (95.6515, 445.931) from edge [end face of Pad1 | face of Chamfer2]
    radius A2 = 3.5
    length L2 = 40
    angle L2 L1 = 165
    length L3 = 40
    distance L5 E1 = 0
    length L4 = 40
    radius A1 = 8.4276
    distance P5 L6 = 87.1944
    length L1 = 36.5609
    coincidence: P1 V, P8 V, A2 P9, P9 L5
    horizontal: L1 H, L5 H
    tangency: A1 L3, A2 L5
    parallelism: L4 L2
    vertical: L6 V
  Pad29: profile Sketch38, direction (-1, 0, 0), length 20
  Mirror11: of Pad29, about zx-plane
  Sketch39 on end face of Pad28, origin (-2080, 0, 0), H (0, -1, 0), V (0, 0, 1)
    line L1 (615, -210) -> (625, -200)
    line L2 (625, -200) -> (645.4504, -200)
    line L3 (645.4504, -200) -> (655, -209.5496)
    line L4 (655, -209.5496) -> (655, -309.5496)
    line L5 (655, -309.5496) -> (644.5496, -320)
    line L6 (644.5496, -320) -> (625, -320)
    line L7 (625, -320) -> (615, -310)
    line L8 (615, -310) -> (615, -210)
    reference projected line E1 (605, -205) -> (605, -315) from edge [face of Pad28 from Sketch37.L12 | end face of Pad28]
    reference projected line E2 (605, -315) -> (665, -315) from edge [face of Pad28 from Sketch37.L11 | end face of Pad28]
    reference projected line E3 (665, -205) -> (605, -205) from edge [face of Pad28 from Sketch37.L9 | end face of Pad28]
    distance L4 L8 = 40
    angle L4 L3 = 135
    distance L8 E1 = 10
    distance L6 E2 = 5
    distance L2 E3 = 5
    length L7 = 14.1421
    length L5 = 14.7792
    length L3 = 13.5051
    length L1 = 14.1421
    horizontal: L2 H, L6 H
    perpendicularity: L3 L1
    vertical: L4 V, L8 V
    parallelism: L5 L1, L7 L3
  Pad30: profile Sketch39, direction (-1, 0, 0), length 20
  Mirror12: of Pad30, about zx-plane
  Plane4: type Angle, RefPlane end face of Pad1, Direction edge [end face of Pad1 | face of Pad28], Angle 30
  Sketch40 on Plane4, origin (-1787.9534, -1032.2754, 0), H (-0.5, 0.866, 0), V (0, 0, 1)
    line L1 (484.0931, 1) -> (364.0931, 1)
    line L2 (364.0931, 1) -> (364.0931, -56)
    line L3 (364.0931, -56) -> (484.0931, -56)
    line L4 (484.0931, -56) -> (484.0931, 1)
    reference projected line E1 (424.763, -63) -> (469.7963, -63) from edge [face of Pad23 from Sketch30.L9 | end face of Pad23]
    reference projected line E2 (424.0931, 39.57) -> (424.0931, -300) from edge [end face of Pad1 | face of Pad28]
    distance L1 L3 = 57
    distance L3 E1 = 7
    distance L4 L2 = 120
    distance L2 E2 = 60
    horizontal: L1 H, L3 H
    vertical: L2 V, L4 V
  Pad31: profile Sketch40, direction (0.866, 0.5, 0), length 129
  Mirror13: of Pad31, about zx-plane
  Sketch41 on face of Pad31, origin (-1787.9534, -1032.2754, 0), H (0.5, -0.866, 0), V (0, 0, 1)
    line L1 (-471.0931, -4) -> (-377.0931, -4)
    line L2 (-377.0931, -4) -> (-377.0931, -51)
    line L3 (-377.0931, -51) -> (-471.0931, -51)
    line L4 (-471.0931, -51) -> (-471.0931, -4)
    reference projected line E1 (-364.0931, -56) -> (-484.0931, -56) from edge [face of Pad31 | face of Pad31 from Sketch40.L3]
    reference projected line E2 (-364.0931, 1) -> (-364.0931, -56) from edge [start face of Pad31 | face of Pad31 from Sketch40.L2]
    distance L1 L3 = 47
    distance L3 E1 = 5
    distance L2 L4 = 94
    distance L2 E2 = 13
    horizontal: L1 H, L3 H
    vertical: L2 V, L4 V
  Pad32: profile Sketch41, direction (-0.866, -0.5, 0), length 32
  Sketch42 on end face of Pad32, origin (-1815.6663, -1048.2754, 0), H (0.5, -0.866, 0), V (0, 0, 1)
    line L1 (-467.5931, -7.5) -> (-427.5931, -7.5)
    line L2 (-427.5931, -7.5) -> (-427.5931, -47.5)
    line L3 (-427.5931, -47.5) -> (-467.5931, -47.5)
    line L4 (-467.5931, -47.5) -> (-467.5931, -7.5)
    point P5 (-420.5931, -7.5)
    line L5 (-420.5931, -7.5) -> (-380.5931, -7.5)
    line L6 (-380.5931, -7.5) -> (-380.5931, -47.5)
    line L7 (-380.5931, -47.5) -> (-420.5931, -47.5)
    line L8 (-420.5931, -47.5) -> (-420.5931, -7.5)
    point P7 (-380.5931, -47.5)
    reference projected line E1 (-471.0931, -4) -> (-471.0931, -51) from edge [face of Pad32 from Sketch41.L4 | end face of Pad32]
    reference projected line E2 (-377.0931, -51) -> (-377.0931, -4) from edge [face of Pad32 from Sketch41.L2 | end face of Pad32]
    reference projected line E3 (-377.0931, -4) -> (-471.0931, -4) from edge [face of Pad32 from Sketch41.L1 | end face of Pad32]
    distance L4 E1 = 3.5
    distance L2 L4 = 40
    distance L8 L6 = 40
    distance L7 L5 = 40
    distance L6 E2 = 3.5
    distance L5 E3 = 3.5
    horizontal: L1 H, L3 H, L5 H, L7 H
    vertical: L2 V, L4 V, L6 V, L8 V
    coincidence: P5 L1, P7 L3
  Pad33: profile Sketch42, direction (-0.866, -0.5, 0), length 3
  Mirror14: of Pad32, about zx-plane
  Mirror15: of Pad33, about zx-plane
  Sketch43 on face of Pad2, origin (0, -263.2631, 362.3506), H (1, 0, 0), V (0, 0.809, 0.5878)
    line L1 (-1835, -558.272) -> (-1835, -478.272)
    line L2 (-1835, -478.272) -> (-1765, -478.272)
    line L3 (-1765, -478.272) -> (-1765, -558.272)
    line L4 (-1765, -558.272) -> (-1835, -558.272)
    reference projected line E1 (-1602.5, -558.272) -> (-2000, -558.272) from edge [face of Pad2 | face of Pocket5 from Sketch28.L9]
    reference projected line E2 (-2000, 184.728) -> (-2000, -695.272) from edge [end face of Pad1 | face of Pad2]
    distance L4 E1 = 0
    distance L1 E2 = 165
    length L2 = 70
    distance L2 L4 = 80
    vertical: L1 V, L3 V
    horizontal: L2 H, L4 H
  Pocket9: profile Sketch43, direction (0, 0.5878, -0.809), length 30
  Mirror16: of Pocket9, about zx-plane
  Sketch44 on face of Pad28, origin (0, -665, 0), H (1, 0, 0), V (0, 0, 1)
    line L1 (-1815, 66) -> (-1815, 1)
    line L2 (-1815, 1) -> (-2010, 1)
    line L3 (-2010, 1) -> (-2010, -315)
    line L4 (-2010, -315) -> (-1880, -315)
    line L5 (-1880, -315) -> (-1880, -200)
    point P6 (-1880, -200)
    line L6 (-1785, 66) -> (-1815, 66)
    reference projected line E1 (-2000, -315) -> (-2080, -315) from edge [face of Pad28 from Sketch37.L10 | face of Pad28 from Sketch37.L11]
    reference projected line E2 (-2010, -182.5) -> (-2010, -137.5) from edge [face of Pad23 from Sketch30.A1 | end face of Pad23]
    reference projected line E3 (-1970, 1) -> (-1858.2827, 1) from edge [face of Pad31 from Sketch40.L2 | face of Pad31 from Sketch40.L1]
    reference projected line E4 (-2000, -63) -> (-2000, 33.3897) from edge [end face of Pad1 | face of Pad28]
    reference projected line E7 (-1880, -56) -> (-1880, 1) from edge [face of Pad28 | face of Pad31 from Sketch40.L2]
    line L7 (-1785, 66) -> (-1785, -66)
    line L8 (-1785, -66) -> (-1685, -66)
    line L9 (-1685, -66) -> (-1685, -91)
    line L10 (-1685, -91) -> (-1785, -91)
    point P11 (-1785, -91)
    line L11 (-1785, -91) -> (-1785, -200)
    line L12 (-1785, -200) -> (-1880, -200)
    point P13 (-1880, -200)
    reference projected line E8 (2945.11, -275) -> (-2000, -275) from edge [face of Pad28 | face of Mirror7]
    reference projected line E9 (-1970, -56) -> (-1858.2827, -56) from edge [face of Pad31 from Sketch40.L3 | face of Pad31 from Sketch40.L2]
    distance L4 E1 = 0
    distance L3 E2 = 0
    distance L2 E3 = 0
    length L1 = 65
    length L6 = 30
    distance L1 E4 = 185
    distance L5 E7 = 0
    distance L12 E8 = 75
    distance L10 L8 = 25
    distance L8 E9 = 10
    distance L9 L7 = 100
    vertical: L1 V, L3 V, L5 V, L7 V, L9 V, L11 V
    horizontal: L2 H, L4 H, L6 H, L8 H, L10 H, L12 H
    coincidence: P11 L7, P13 L5, P13 P6
  Pad34: profile Sketch44, direction (0, -1, 0), length 30
  Mirror17: of Pad34, about zx-plane
  Sketch45 on face of Pad2, origin (0, -263.2631, 362.3506), H (1, 0, 0), V (0, 0.809, 0.5878)
    line L1 (525, -462.772) -> (525, -542.772)
    line L2 (525, -542.772) -> (595, -542.772)
    line L3 (595, -542.772) -> (595, -462.772)
    line L4 (595, -462.772) -> (525, -462.772)
    reference projected line E1 (682.5, -621.272) -> (-24, -621.272) from edge [face of Pad2 | face of Pocket5 from Sketch28.L17]
    reference projected line E2 (682.5, 153.328) -> (682.5, -621.272) from edge [face of Pad2 | face of Pocket5 from Sketch28.L18]
    distance L2 E1 = 78.5
    distance L3 E2 = 87.5
    length L3 = 80
    distance L1 L3 = 70
    vertical: L1 V, L3 V
    horizontal: L2 H, L4 H
  Pocket10: profile Sketch45, direction (0, 0.5878, -0.809), length 30
  Mirror18: of Pocket10, about zx-plane
  Sketch46 on face of Pad28, origin (0, -665, 0), H (1, 0, 0), V (0, 0, 1)
    line L1 (545, -13.0493) -> (545, 73.3173)
    line L2 (545, 73.3173) -> (575, 73.3173)
    line L3 (575, 73.3173) -> (575, -13.0493)
    line L4 (575, -13.0493) -> (545, -13.0493)
    reference projected line E1 (595, 43.3173) -> (595, 90.3401) from edge [face of Pad2 | face of Pocket10 from Sketch45.L3]
    reference projected line E2 (682.5, -23.0493) -> (-24, -23.0493) from edge [face of Pocket5 from Sketch28.L17 | face of Pad2]
    reference projected line E3 (525, 43.3173) -> (595, 43.3173) from edge [face of Pad2 | face of Pocket10 from Sketch45.L2]
    length L2 = 30
    distance L3 E1 = 20
    distance L4 E2 = 10
    distance L2 E3 = 30
    vertical: L1 V, L3 V
    horizontal: L2 H, L4 H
